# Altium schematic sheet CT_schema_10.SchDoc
size 274 x 160 mm
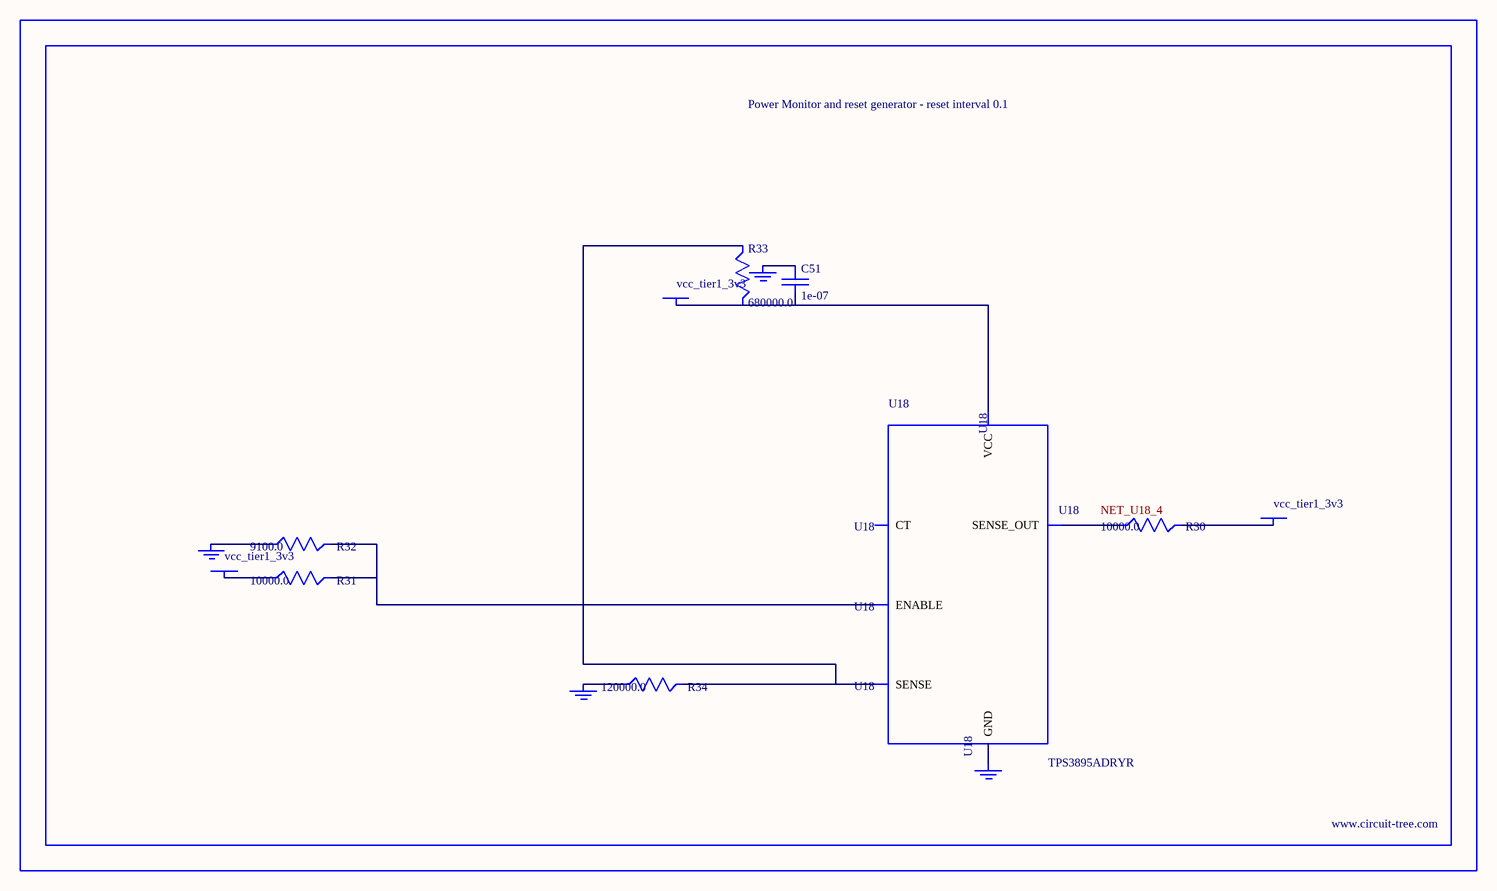
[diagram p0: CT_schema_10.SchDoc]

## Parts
BORDER9  (no value)
C51  1e-07  [C0402]
GND_INSTANCE_9_0  (no value)
GND_INSTANCE_9_1  (no value)
GND_INSTANCE_9_2  (no value)
GND_INSTANCE_9_3  (no value)
POWER_INSTANCE_9_0  vcc_tier1_3v3
POWER_INSTANCE_9_1  vcc_tier1_3v3
POWER_INSTANCE_9_2  vcc_tier1_3v3
R30  10000.0  [R0603]
R31  10000.0  [R0603]
R32  9100.0  [R0603]
R33  680000.0  [R0603]
R34  120000.0  [R0603]
U18  TPS3895ADRYR  [SON-6]

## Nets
NetC51_1: C51.1 GND_INSTANCE_9_2.0(GND)
NetC51_2: C51.2 POWER_INSTANCE_9_2.0(PWR) R33.2 U18.6(VCC)
NetGND_INSTANCE_9_0_0: GND_INSTANCE_9_0.0(GND) R32.1
NetGND_INSTANCE_9_1_0: GND_INSTANCE_9_1.0(GND) R34.1
NetGND_INSTANCE_9_3_0: GND_INSTANCE_9_3.0(GND) U18.2(GND)
NetPOWER_INSTANCE_9_0_0: POWER_INSTANCE_9_0.0(PWR) R31.1
NetPOWER_INSTANCE_9_1_0: POWER_INSTANCE_9_1.0(PWR) R30.2
NetR30_1: R30.1 U18.4(SENSE_OUT)
NetR31_2: R31.2 R32.2 U18.1(ENABLE)
NetR33_1: R33.1 R34.2 U18.3(SENSE)

Not connected (* = marked no-connect by the designer): U18 5(CT)

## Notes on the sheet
- Labels drawn without touching a wire or pin: NET_U18_4

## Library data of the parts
BORDER9 = BORDER_PAGE9
C51 = C0402C104K3RACTU
GND_INSTANCE_9_0-GND_INSTANCE_9_3 = GND
POWER_INSTANCE_9_0-POWER_INSTANCE_9_2 = PWR
R30 R31 = RC0603JR-0710KL
R32 = RC0603JR-079K1L
R33 = RC0603JR-07680KL
R34 = RC0603JR-07120KL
